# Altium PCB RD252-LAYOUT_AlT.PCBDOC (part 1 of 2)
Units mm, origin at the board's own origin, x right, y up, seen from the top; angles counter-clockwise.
Board outline 55 x 54 mm, 2 copper layers (TOP, BOTTOM), stack 0 mm thick; 81 components, 42 nets, 652 pads, 0 vias.
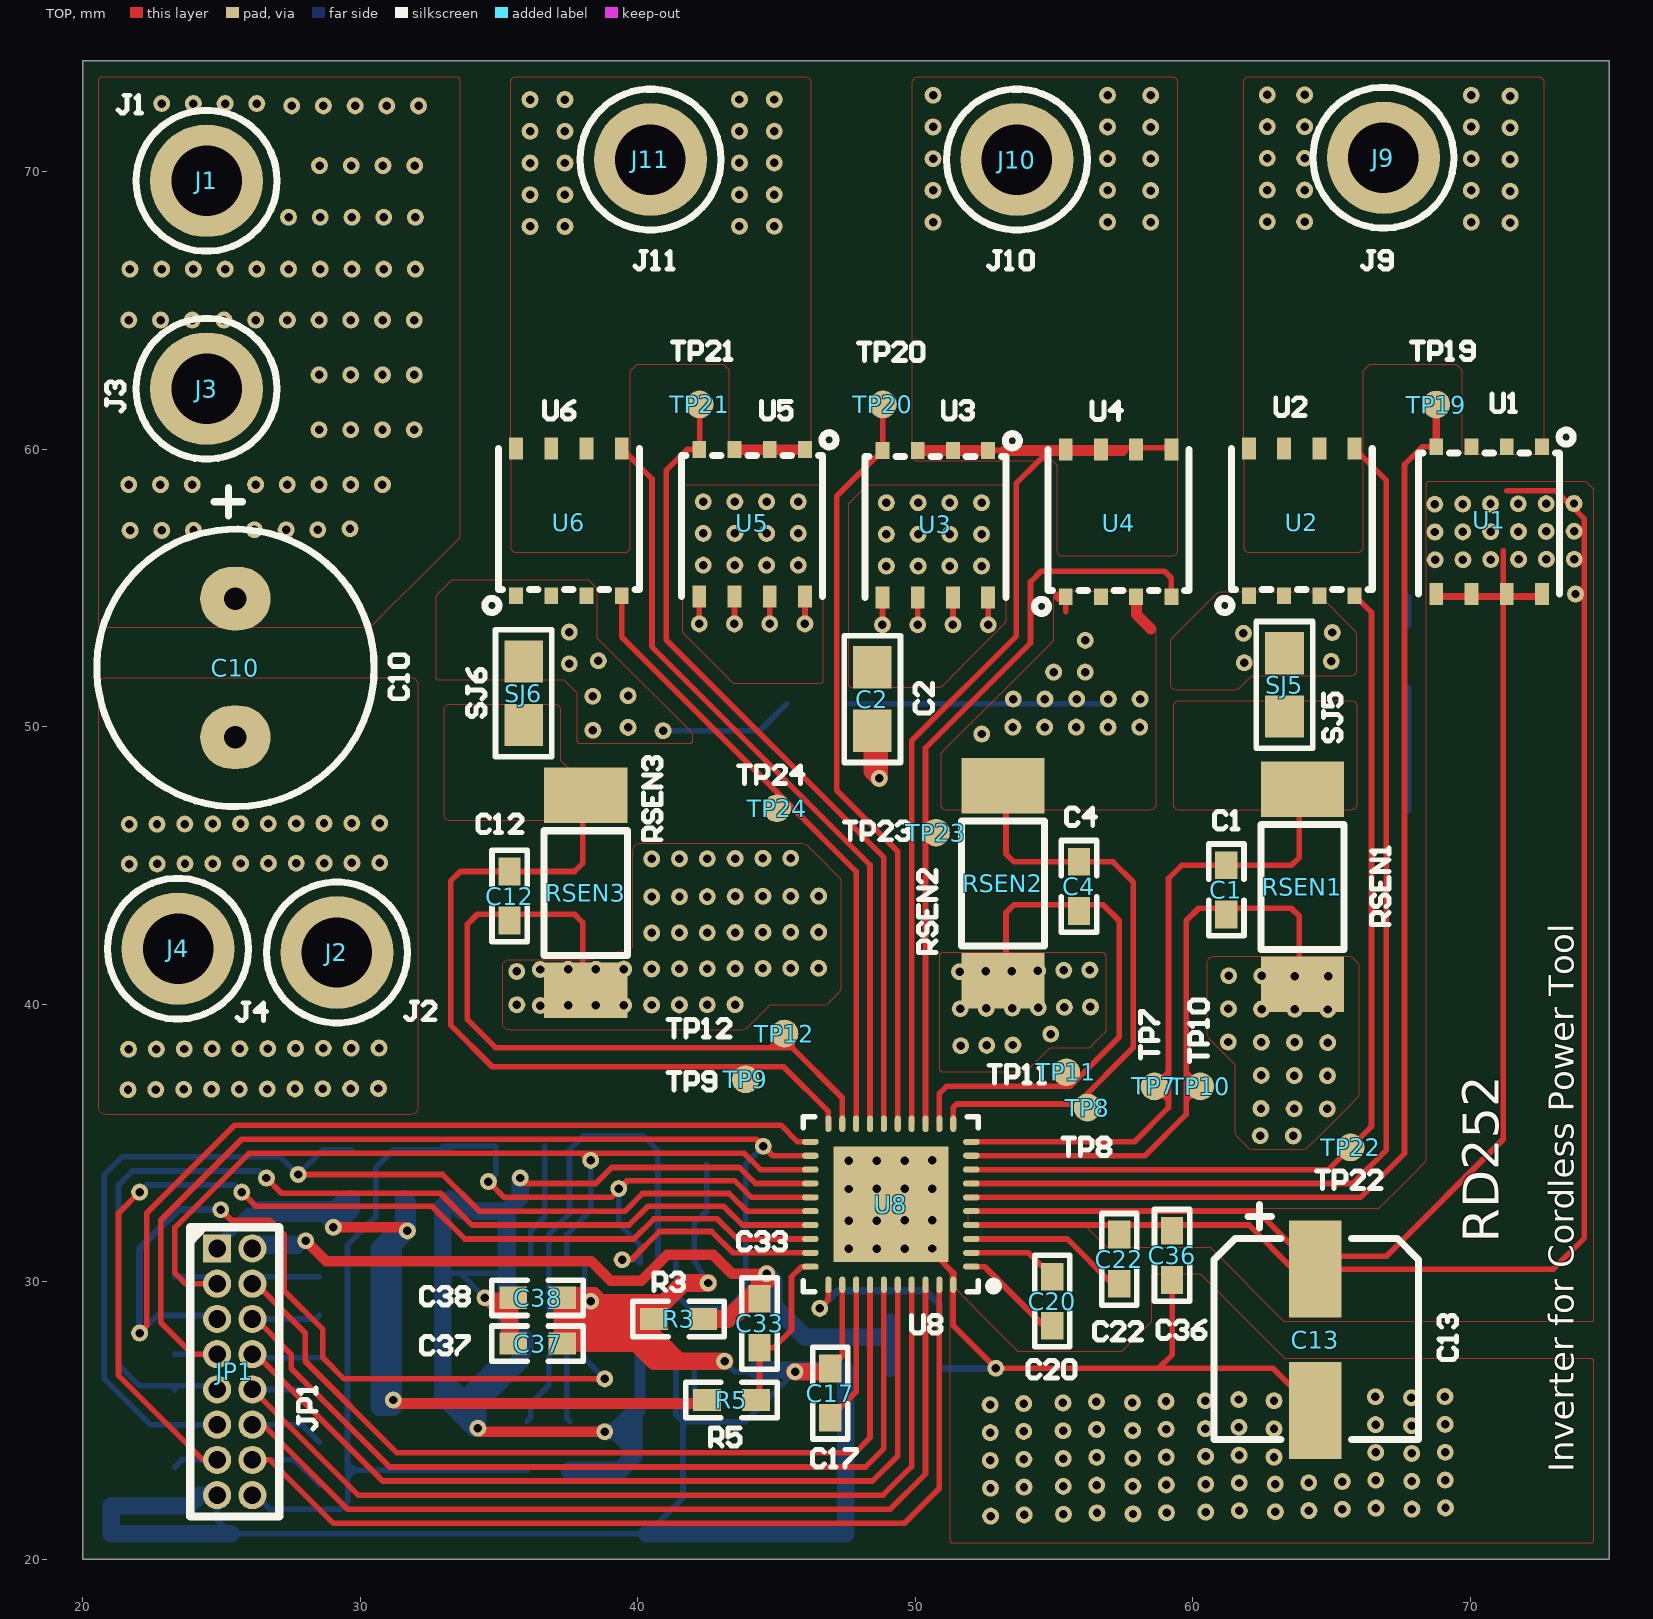
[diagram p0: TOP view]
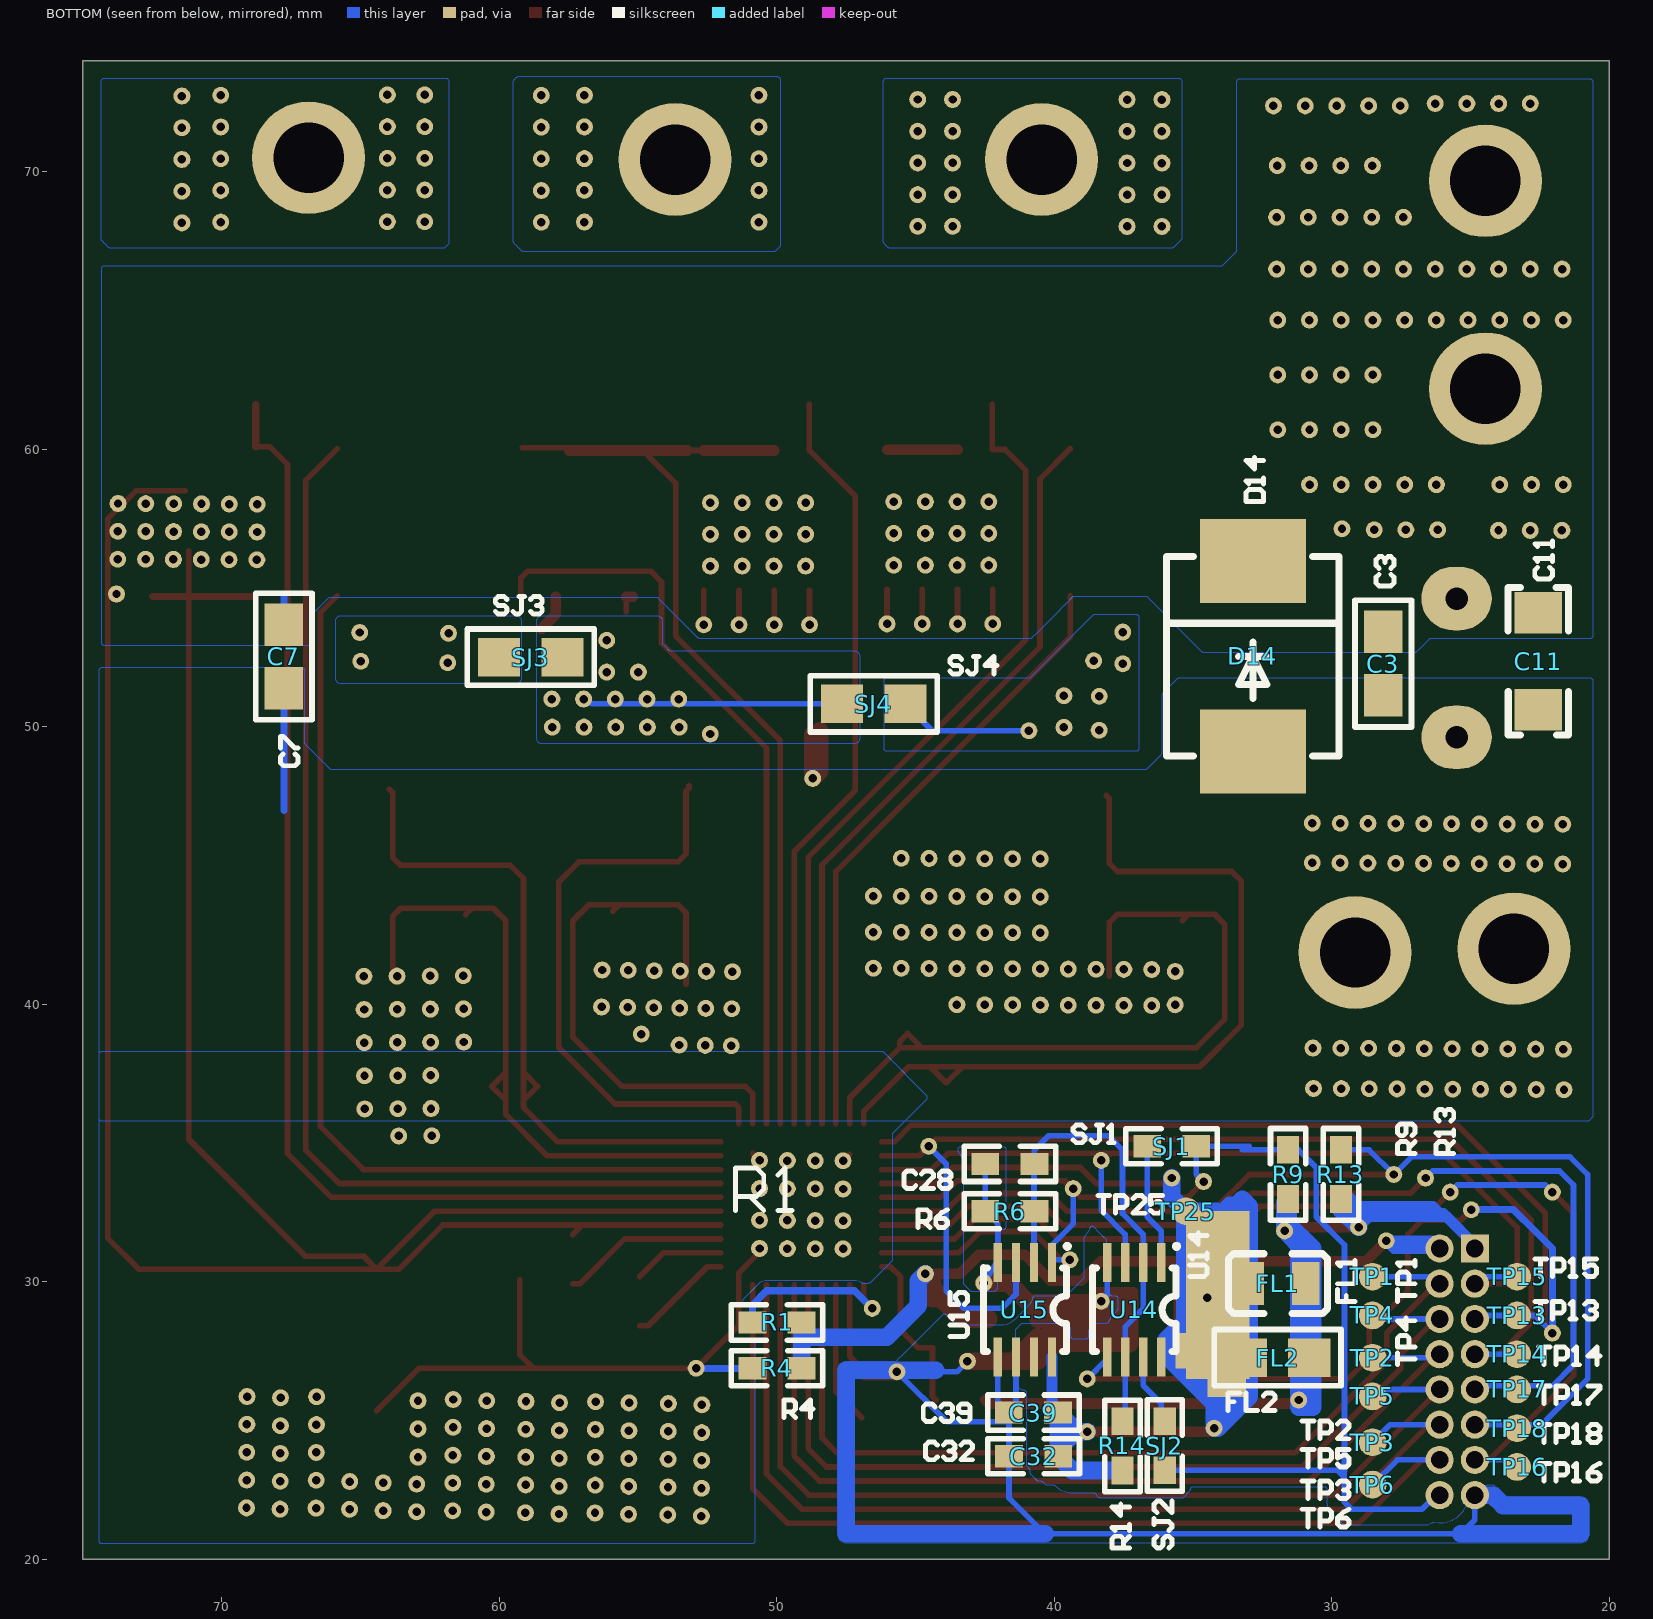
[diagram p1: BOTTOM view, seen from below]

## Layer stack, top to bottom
Top Solder: solder mask 0.0102, Solder Resist, Dk 3.5
TOP: signal copper (thickness not stored)
BOTTOM: signal copper (thickness not stored)
Bottom Solder: solder mask 0.0102, Solder Resist, Dk 3.5

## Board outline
20,20 20,74 75,74 75,20

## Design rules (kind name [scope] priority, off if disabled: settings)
AssemblyTestPointUsage [All] p0: scope1count=1 scope1_0_kind=Board scope1_0_value=Board scope2count=1 scope2_0_kind=Board scope2_0_value=Board commentlength=0
AssemblyTestpoint [All] p0: scope1count=1 scope1_0_kind=Board scope1_0_value=Board scope2count=1 scope2_0_kind=Board scope2_0_value=Board commentlength=0
Clearance [All] p0: scope1count=1 scope1_0_kind=Board scope1_0_value=Board scope2count=1 scope2_0_kind=Board scope2_0_value=Board commentlength=0 gap=0.15
Clearance [All] p1: gap=0.15 ignorepadtopadclearanceinfootprint=TRUE except(0.2: SMDPad-Fill SMDPad-Poly SMDPad-Region THPad-Fill THPad-Poly THPad-Region; 0.3: Arc-Hole Track-Hole SMDPad-Hole THPad-Hole Via-Hole Fill-Hole Poly-Hole Region-Hole Text-Hole)
ComponentClearance [All] p0: scope1count=1 scope1_0_kind=Board scope1_0_value=Board scope2count=1 scope2_0_kind=Board scope2_0_value=Board commentlength=0 gap=0.254 collisioncheckmode=3
DiffPairsRouting [All] p0: scope1count=1 scope1_0_kind=Board scope1_0_value=Board scope2count=1 scope2_0_kind=Board scope2_0_value=Board commentlength=0
FabricationTestPointUsage [All] p0: scope1count=1 scope1_0_kind=Board scope1_0_value=Board scope2count=1 scope2_0_kind=Board scope2_0_value=Board commentlength=0 valid=0 allowmultiple=FALSE
FabricationTestpoint [All] p0: scope1count=1 scope1_0_kind=Board scope1_0_value=Board scope2count=1 scope2_0_kind=Board scope2_0_value=Board commentlength=0 side=3 testpointundercomponent=TRUE minsize=1.016 maxsize=2.54 preferedsize=1.524 minholesize=0 maxholesize=1.016 preferedholesize=0.813 testpointgrid=0.025
FanoutControl Fanout_Default [All] p0: scope1count=1 scope1_0_kind=Board scope1_0_value=Board scope2count=1 scope2_0_kind=Board scope2_0_value=Board commentlength=30 // Fanout_Default (Default Rule)
FanoutControl Fanout_Small [All] p0 off: scope1count=1 scope1_0_kind=Board scope1_0_value=Board scope2count=1 scope2_0_kind=Board scope2_0_value=Board commentlength=84 // Protel DXP Scope 1 Expression Was: (CompPinCount < 5)   Fanout_Small (Default Rule)
FanoutControl Fanout_SOIC [All] p0 off: scope1count=1 scope1_0_kind=Board scope1_0_value=Board scope2count=1 scope2_0_kind=Board scope2_0_value=Board commentlength=71 // Protel DXP Scope 1 Expression Was: IsSOIC   Fanout_SOIC (Default Rule)
FanoutControl Fanout_LCC [All] p0 off: scope1count=1 scope1_0_kind=Board scope1_0_value=Board scope2count=1 scope2_0_kind=Board scope2_0_value=Board commentlength=69 // Protel DXP Scope 1 Expression Was: IsLCC   Fanout_LCC (Default Rule)
FanoutControl Fanout_BGA [All] p0 off: scope1count=1 scope1_0_kind=Board scope1_0_value=Board scope2count=1 scope2_0_kind=Board scope2_0_value=Board commentlength=69 // Protel DXP Scope 1 Expression Was: IsBGA   Fanout_BGA (Default Rule)
Height [All] p0: scope1count=1 scope1_0_kind=Board scope1_0_value=Board scope2count=1 scope2_0_kind=Board scope2_0_value=Board commentlength=0
HoleSize [All] p0: scope1count=1 scope1_0_kind=Board scope1_0_value=Board scope2count=1 scope2_0_kind=Board scope2_0_value=Board commentlength=0 absolutevalues=TRUE maxlimit=100 minlimit=0.001 maxpercent=80.000 minpercent=20.000
HoleSize [All] p1: absolutevalues=TRUE maxlimit=100 minlimit=0.001 maxpercent=80.000 minpercent=20.000
HoleToHoleClearance [All] p0: scope1count=1 scope1_0_kind=Board scope1_0_value=Board scope2count=1 scope2_0_kind=Board scope2_0_value=Board commentlength=0
HoleToHoleClearance [All] p1: gap=0.4 allowstackedmicrovias=FALSE
LayerPairs [All] p0: scope1count=1 scope1_0_kind=Board scope1_0_value=Board scope2count=1 scope2_0_kind=Board scope2_0_value=Board commentlength=0 enforce=TRUE
MinimumSolderMaskSliver [All] p0: scope1count=1 scope1_0_kind=Board scope1_0_value=Board scope2count=1 scope2_0_kind=Board scope2_0_value=Board commentlength=0
MinimumSolderMaskSliver [All] p1: minsoldermaskwidth=0.1
NetAntennae [All] p0: scope1count=1 scope1_0_kind=Board scope1_0_value=Board scope2count=1 scope2_0_kind=Board scope2_0_value=Board commentlength=0
NetAntennae [All] p1: netantennaetolerance=100
PasteMaskExpansion [All] p0: scope1count=1 scope1_0_kind=Board scope1_0_value=Board scope2count=1 scope2_0_kind=Board scope2_0_value=Board commentlength=0 expansion=0
PlaneClearance [All] p0: scope1count=1 scope1_0_kind=Board scope1_0_value=Board scope2count=1 scope2_0_kind=Board scope2_0_value=Board commentlength=0 clearance=0.001
PlaneClearance [All] p1: clearance=0.001
PlaneConnect [All] p0: scope1count=1 scope1_0_kind=Board scope1_0_value=Board scope2count=1 scope2_0_kind=Board scope2_0_value=Board commentlength=0 planeconnectstyle=Direct reliefexpansion=0.508 reliefentries=4 reliefconductorwidth=0.254 reliefairgap=0.254
PlaneConnect [All] p1: planeconnectstyle=Direct reliefexpansion=0.508 reliefentries=4 reliefconductorwidth=0.254 reliefairgap=0.254
PolygonConnect [All] p0: scope1count=1 scope1_0_kind=Board scope1_0_value=Board scope2count=1 scope2_0_kind=Board scope2_0_value=Board commentlength=0 connectstyle=Direct reliefconductorwidth=0.254 reliefentries=4 polygonreliefangle="90 Angle"
PolygonConnect [All] p1: connectstyle=Direct reliefconductorwidth=0.254 reliefentries=4 polygonreliefangle="90 Angle" airgapwidth=0.254
RoutingCorners [All] p0: scope1count=1 scope1_0_kind=Board scope1_0_value=Board scope2count=1 scope2_0_kind=Board scope2_0_value=Board commentlength=0 cornerstyle=45-Degree minsetback=2.54 maxsetback=2.54
RoutingLayers [All] p0: scope1count=1 scope1_0_kind=Board scope1_0_value=Board scope2count=1 scope2_0_kind=Board scope2_0_value=Board commentlength=0 top layer=Automatic bottom layer=Automatic
RoutingPriority [All] p0: scope1count=1 scope1_0_kind=Board scope1_0_value=Board scope2count=1 scope2_0_kind=Board scope2_0_value=Board commentlength=0
RoutingTopology [All] p0: scope1count=1 scope1_0_kind=Board scope1_0_value=Board scope2count=1 scope2_0_kind=Board scope2_0_value=Board commentlength=0 topology=Shortest
RoutingVias [All] p0: scope1count=1 scope1_0_kind=Board scope1_0_value=Board scope2count=1 scope2_0_kind=Board scope2_0_value=Board commentlength=0 holewidth=0.1 width=0.1 viastyle="Through Hole" minholewidth=0.001 minwidth=0.001 maxholewidth=100 maxwidth=100
RoutingVias [All] p1: holewidth=0.1 width=0.1 viastyle="Through Hole" minholewidth=0.001 minwidth=0.001 maxholewidth=100 maxwidth=100
ShortCircuit [All] p0: scope1count=1 scope1_0_kind=Board scope1_0_value=Board scope2count=1 scope2_0_kind=Board scope2_0_value=Board commentlength=0 allowed=FALSE
SilkToBoardRegionClearance [All] p0: scope1count=1 scope1_0_kind=Board scope1_0_value=Board scope2count=1 scope2_0_kind=Board scope2_0_value=Board commentlength=0
SilkToSilkClearance [All] p0: scope1count=1 scope1_0_kind=Board scope1_0_value=Board scope2count=1 scope2_0_kind=Board scope2_0_value=Board commentlength=0
SilkToSilkClearance [All] p1: silktosilkclearance=0.001
SilkToSolderMaskClearance [All] p0 off: scope1count=1 scope1_0_kind=Board scope1_0_value=Board scope2count=1 scope2_0_kind=Board scope2_0_value=Board commentlength=44 // Protel DXP Scope 1 Expression Was: IsPad
SilkToSolderMaskClearance [IsPad] p1: minsilkscreentomaskgap=0 clearancetoexposedcopper=TRUE
SolderMaskExpansion [All] p0: scope1count=1 scope1_0_kind=Board scope1_0_value=Board scope2count=1 scope2_0_kind=Board scope2_0_value=Board commentlength=0 expansion=0.001
SolderMaskExpansion [All] p1: expansion=0.001
UnRoutedNet [All] p0: scope1count=1 scope1_0_kind=Board scope1_0_value=Board scope2count=1 scope2_0_kind=Board scope2_0_value=Board commentlength=0
UnpouredPolygon [All] p0: scope1count=1 scope1_0_kind=Board scope1_0_value=Board scope2count=1 scope2_0_kind=Board scope2_0_value=Board commentlength=0
Width [All] p0: scope1count=1 scope1_0_kind=Board scope1_0_value=Board scope2count=1 scope2_0_kind=Board scope2_0_value=Board commentlength=0 maxlimit=1000 minlimit=2539.975 preferedwidth=0
Width [All] p1: maxlimit=1000 minlimit=2539.975 preferedwidth=0 toplayer_minwidth=0 bottomlayer_minwidth=0 minimp=50.000000 maximp=50.000000 favimp=50.000000
22 further rules are at their usual default settings.

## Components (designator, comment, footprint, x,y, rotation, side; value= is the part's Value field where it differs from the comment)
C1 "0603" 0603#1 61.208,45.009 r270 top
C2 "0805" 0805#1 48.448,52.147 r270 top
C3 "0805" 0805#2 28.137,53.426 r90 bottom
C4 "0603" 0603#1 55.899,45.136 r270 top
C7 "0805" 0805#2 67.761,53.68 r90 bottom
C10 "CAP_10MM" CAP_10MM 25.495,54.626 r180 top
C11 "1206" 1206 22.549,54.115 r270 bottom
C12 "0603" 0603#1 35.376,44.79 r270 top
C13 "CASE_B2" CASE_B2 64.416,30.455 r270 top
C17 "0603" 0603#1 46.933,25.105 r90 top
C20 "0603" 0603#1 54.934,30.185 r270 top
C22 "0603" 0603#1 57.347,29.931 r90 top
C32 "0603" 0603#2 39.853,23.711 r180 bottom
C33 "0603" 0603#1 44.384,27.62 r90 top
C36 "0603" 0603#1 59.252,31.836 r270 top
C37 "0603" 0603#1 35.503,27.772 r0 top
C38 "0603" 0603#1 35.503,29.423 r0 top
C39 "0603" 0603#2 39.861,25.286 r180 bottom
D14 "DSMC" DSMC 32.836,49.108 r90 bottom
FL1 "L0805" L0805 30.931,29.931 r180 bottom
FL2 "0805" 0805#2 33.09,27.264 r0 bottom
J1 "TP_SM" TP_SM 24.454,69.682 r180 top
J2 "TP_SM" TP_SM 29.153,41.869 r180 top
J3 "TP_SM" TP_SM 24.454,62.189 r0 top
J4 "TP_SM" TP_SM 23.425,42.004 r0 top
J9 "TP_SM" TP_SM 66.869,70.514 r0 top
J10 "TP_SM" TP_SM 53.661,70.446 r0 top
J11 "TP_SM" TP_SM 40.453,70.446 r0 top
JP1 "IDC16_1.27MM" IDC16_1.27MM 24.835,31.201 r270 top
R1 "0603" 0603#2 50.87,28.534 r0 bottom
R3 "0603" 0603#1 40.583,28.661 r0 top
R4 "0603" 0603#2 49.104,26.883 r180 bottom
R5 "0603" 0603#1 42.488,25.74 r0 top
R6 "0603" 0603#2 40.71,32.545 r180 bottom
R9 "0603" 0603#2 31.566,34.757 r90 bottom
R13 "0603" 0603#2 29.661,34.757 r90 bottom
R14 "0603" 0603#2 37.535,23.2 r270 bottom
RSEN1 "2512" 2512 63.951,40.726 r270 top
RSEN2 "2512" 2512 53.156,40.853 r270 top
RSEN3 "2512" 2512 38.119,40.507 r270 top
SJ1 "0603" 0603#2 36.646,34.884 r0 bottom
SJ2 "0603" 0603#2 36.011,24.978 r90 bottom
SJ3 "0805" 0805#2 60.006,52.514 r0 bottom
SJ4 "0805" 0805#2 47.644,50.83 r0 bottom
SJ5 "0805" 0805#1 63.307,50.371 r90 top
SJ6 "0805" 0805#1 35.883,50.068 r90 top
TP1 "TP2" TP2 28.518,30.185 r180 bottom
TP2 "TP2" TP2 28.518,27.264 r180 bottom
TP3 "TP2" TP2 28.518,24.216 r180 bottom
TP4 "TP2" TP2 28.518,28.788 r90 bottom
TP5 "TP2" TP2 28.518,25.867 r90 bottom
TP6 "TP2" TP2 28.518,22.692 r90 bottom
TP7 "TP2" TP2 58.617,37.043 r0 top
TP8 "TP2" TP2 56.204,36.281 r180 top
TP9 "TP2" TP2 43.885,37.297 r180 top
TP10 "TP2" TP2 60.268,37.043 r180 top
TP11 "TP2" TP2 55.442,37.551 r180 top
TP12 "TP2" TP2 45.282,38.948 r270 top
TP13 "TP2" TP2 23.311,28.788 r270 bottom
TP14 "TP2" TP2 23.311,27.391 r270 bottom
TP15 "TP2" TP2 23.311,30.185 r270 bottom
TP16 "TP2" TP2 23.311,23.327 r270 bottom
TP17 "TP2" TP2 23.311,26.121 r270 bottom
TP18 "TP2" TP2 23.311,24.724 r270 bottom
TP19 "TP2" TP2 68.774,61.617 r0 top
TP20 "TP2" TP2 48.829,61.621 r180 top
TP21 "TP2" TP2 42.225,61.621 r180 top
TP22 "TP2" TP2 65.687,34.842 r180 top
TP23 "TP2" TP2 50.743,46.187 r180 top
TP24 "TP2" TP2 45.019,47.067 r180 top
TP25 "TP2" TP2 35.249,32.545 r270 bottom
U1 "SOP-8T" SOP-8T 72.584,60.093 r0 top
U2 "SOP-8T" SOP-8T 62.022,54.729 r180 top
U3 "SOP-8T" SOP-8T 52.624,59.961 r0 top
U4 "SOP-8T" SOP-8T 55.418,54.695 r180 top
U5 "SOP-8T_1" SOP-8T_1 46.02,59.995 r0 top
U6 "SOP-8T" SOP-8T 35.607,54.729 r180 top
U8 "WQFN-40" WQFN-40 52.016,30.545 r180 top
U14 "SSOP-8" SSOP-8 36.138,30.693 r180 bottom
U15 "SSOP-8" SSOP-8 40.075,30.693 r180 bottom
? "0603" 0603#2 40.71,34.249 r180 bottom

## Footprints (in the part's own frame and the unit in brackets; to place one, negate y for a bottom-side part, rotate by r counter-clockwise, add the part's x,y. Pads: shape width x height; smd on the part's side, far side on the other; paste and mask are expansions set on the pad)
0603#1 [mm] "KC00080BKP"
  rect 1x0.8 smd paste-1.203 mask+0: 1(0,0) 2(1.77,0)
0603#2 [mm] "KC00080BKP"
  rect 1x0.8 smd paste-1.203 mask+0: 1(0,0) 2(-1.77,0)
0805#1 [mil] "KC00080BKP"
  rect 60x55 smd paste-68 mask+0: 1(0,0) 2(90,0)
0805#2 [mil] "KC00080BKP"
  rect 60x55 smd paste-68 mask+0: 1(0,0) 2(-90,0)
1206 [mm] "KC00080BKP"
  rect 1.5x1.7 smd paste-1.903 mask+0: 1(0,0) 2(3.5,0)
2512 [mm] "KC00080BKP"
  rect 2x3 smd paste-3.203 mask+0: 1(0,0) 2(-7.021,0)
CAP_10MM [mil] "KC00080BKP"
  oval 100x90 / inner round 0 / far side oval 100x90 hole 32 paste-108 mask+0: 1(0,0) 2(0,196.85)
CASE_B2 [mm] "KC00080BKP"
  rect 3.5x1.9 smd paste-3.6 mask+0: 1(0,0) 2(5.1,0)
DSMC [mm] "KC00080BKP"
  rect 3.03x3.82 smd paste-4.023 mask+0: A(0,0) C(6.87,0)
IDC16_1.27MM [mil] "KC00080BKP"
  rect 40x40 / inner round 0 / far side rect 40x40 hole 25 paste-48 mask+0: 1(0,0)
  round 40 / inner round 0 / far side round 40 hole 25 paste-48 mask+0: 2(0,50) 3(50,0) 4(50,50) 5(100,0) 6(100,50) 7(150,0) 8(150,50) 9(200,0) 10(200,50) 11(250,0) 12(250,50) 13(300,0) 14(300,50) 15(350,0) 16(350,50)
L0805 [mm] "KC00080BKP"
  rect 1x1.55 smd paste-1.753 mask+0: 1(0,0) 2(-2,0)
SOP-8T [mm] "KC00080BKP"
  rect 0.5x0.6 smd paste-0.803 mask+0: 1(0,0) 2(-1.27,0) 3(-2.54,0) 4(-3.81,0)
  rect 0.5x0.8 smd paste-1.003 mask+0: 5(-3.81,-5.3) 6(-2.54,-5.3) 7(-1.27,-5.3) 8(0,-5.3)
SOP-8T_1 [mm] "KC00080BKP"
  rect 0.5x0.6 smd paste-0.803 mask+0: 1(0,0) 2(-1.27,0) 3(-2.54,0) 4(-3.81,0)
  rect 0.5x0.8 smd paste-1.003 mask+0: 5(-3.81,-5.3) 6(-2.54,-5.3) 7(-1.27,-5.3) 8(0,-5.3)
SSOP-8 [mm] "KC00080BKP"
  rect 0.3x1.4 smd paste-1.603 mask+0: 1(0,0) 2(-0.65,0) 3(-1.3,0) 4(-1.95,0) 5(-1.95,-3.4) 6(-1.3,-3.4) 7(-0.65,-3.4) 8(0,-3.4)
TP2 [mm] "KC00080BKP"
  round 1 smd paste-1.203 mask+0: 1(0,0)
TP_SM [mil] "KC00080BKP"
  round 160 / inner round 0 / far side round 160 hole 100 paste-168 mask+0: 1(0,0)
WQFN-40 [mm] "KC00080BKP"
  oval 0.6x0.22 smd paste-0.803 mask+0: 1(0,0) 2(0,-0.5) 3(0,-1) 4(0,-1.5) 5(0,-2) 6(0,-2.5) 7(0,-3) 8(0,-3.5) 9(0,-4) 10(0,-4.5) 21(5.8,-4.5) 22(5.8,-4) 23(5.8,-3.5) 24(5.8,-3) 25(5.8,-2.5) 26(5.8,-2) 27(5.8,-1.5) 28(5.8,-1) 29(5.8,-0.5) 30(5.8,0)
  oval 0.22x0.6 smd paste-0.803 mask+0: 11(0.65,-5.15) 12(1.15,-5.15) 13(1.65,-5.15) 14(2.15,-5.15) 15(2.65,-5.15) 16(3.15,-5.15) 17(3.65,-5.15) 18(4.15,-5.15) 19(4.65,-5.15) 20(5.15,-5.15) 31(5.15,0.65) 32(4.65,0.65) 33(4.15,0.65) 34(3.65,0.65) 35(3.15,0.65) 36(2.65,0.65) 37(2.15,0.65) 38(1.65,0.65) 39(1.15,0.65) 40(0.65,0.65)
  rect 4.15x4.15 smd paste-4.353 mask+0: 41(2.9,-2.25)

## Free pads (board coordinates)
  round 0.61 / inner round 0 / far side round 0.61 hole 0.305 paste-0.813 mask+0: ""(21.623,36.924) ""(21.643,38.381) ""(21.649,58.732) ""(21.653,64.663) ""(21.665,46.489) ""(21.67,45.057) ""(21.693,66.5) ""(21.697,57.081) ""(22.041,28.153) ""(22.041,33.233) ""(22.626,36.929) ""(22.646,38.386) ""(22.668,46.494) ""(22.673,45.062) ""(22.792,58.732) ""(22.796,64.663) ""(22.836,66.5) ""(22.836,72.466) ""(22.84,57.081) ""(23.629,36.934) ""(23.649,38.391) ""(23.671,46.499) ""(23.676,45.067) ""(23.935,58.732) ""(23.939,64.663) ""(23.979,66.5) ""(23.979,72.466) ""(23.983,57.081) ""(24.632,36.939) ""(24.652,38.396) ""(24.674,46.503) ""(24.679,45.071) ""(24.962,32.598) ""(25.082,64.663) ""(25.122,66.5) ""(25.122,72.466) ""(25.635,36.943) ""(25.655,38.4) ""(25.677,46.508) ""(25.682,45.076) ""(25.724,33.233) ""(26.178,57.107) ""(26.221,58.732) ""(26.225,64.663) ""(26.265,66.5) ""(26.265,72.466) ""(26.613,33.741) ""(26.638,36.948) ""(26.658,38.405) ""(26.68,46.513) ""(26.685,45.081) ""(27.321,57.107) ""(27.364,58.732) ""(27.368,64.663) ""(27.408,66.5) ""(27.409,68.367) ""(27.522,72.382) ""(27.641,36.953) ""(27.661,38.41) ""(27.683,46.518) ""(27.688,45.086) ""(27.756,33.868) ""(28.026,31.481) ""(28.464,57.107) ""(28.507,58.732) ""(28.508,60.709) ""(28.509,62.686) ""(28.511,64.663) ""(28.526,70.229) ""(28.551,66.5) ""(28.552,68.367) ""(28.644,36.958) ""(28.664,38.415) ""(28.665,72.382) ""(28.686,46.523) ""(28.691,45.091) ""(29.026,31.963) ""(29.624,57.139) ""(29.646,36.963) ""(29.65,58.732) ""(29.651,60.709) ""(29.652,62.686) ""(29.654,64.663) ""(29.667,38.42) ""(29.669,70.229) ""(29.689,46.527) ""(29.694,45.095) ""(29.694,66.5) ""(29.695,68.367) ""(29.808,72.382) ""(30.649,36.968) ""(30.67,38.425) ""(30.692,46.532) ""(30.697,45.1) ""(30.793,58.732) ""(30.794,60.709) ""(30.795,62.686) ""(30.797,64.663) ""(30.812,70.229) ""(30.837,66.5) ""(30.838,68.367) ""(30.951,72.382) ""(31.185,25.74) ""(31.693,31.836) ""(31.937,60.709) ""(31.938,62.686) ""(31.94,64.663) ""(31.955,70.229) ""(31.98,66.5) ""(31.981,68.367) ""(32.094,72.382) ""(34.233,24.724) ""(34.487,29.423) ""(34.614,33.614) ""(35.633,41.186) ""(35.638,39.984) ""(35.757,33.741) ""(36.114,68.036) ""(36.114,69.179) ""(36.114,70.322) ""(36.114,71.465) ""(36.114,72.608) ""(36.482,39.957) ""(36.482,41.256) ""(37.371,68.037) ""(37.371,69.18) ""(37.371,70.323) ""(37.371,71.466) ""(37.371,72.609) ""(37.484,39.961) ""(37.485,41.261) ""(37.526,52.274) ""(37.526,53.417) ""(38.297,29.296) ""(38.297,34.376) ""(38.37,51.102) ""(38.378,49.878) ""(38.487,39.966) ""(38.488,41.265) ""(38.576,52.385) ""(38.805,24.597) ""(38.805,26.502) ""(39.313,33.36) ""(39.431,30.795) ""(39.49,39.971) ""(39.491,41.27) ""(39.645,49.982) ""(39.645,51.125) ""(40.493,39.976) ""(40.494,41.275) ""(40.495,42.574) ""(40.495,45.241) ""(40.496,43.873) ""(40.908,49.863) ""(41.496,39.981) ""(41.497,41.28) ""(41.498,42.579) ""(41.498,45.246) ""(41.499,43.878) ""(42.21,53.712) ""(42.352,55.83) ""(42.352,56.973) ""(42.352,58.116) ""(42.499,39.985) ""(42.5,41.285) ""(42.501,42.584) ""(42.501,45.251) ""(42.502,43.883) ""(42.53,29.957) ""(43.123,27.137) ""(43.48,53.712) ""(43.495,55.83) ""(43.495,56.973) ""(43.495,58.116) ""(43.502,39.99) ""(43.503,41.289) ""(43.504,42.589) ""(43.504,45.256) ""(43.505,43.888) ""(43.66,68.04) ""(43.66,69.183) ""(43.66,70.326) ""(43.66,71.469) ""(43.66,72.612) ""(44.506,41.294) ""(44.507,42.593) ""(44.507,45.26) ""(44.508,43.893) ""(44.52,34.884) ""(44.638,30.287) ""(44.638,55.83) ""(44.638,56.973) ""(44.638,58.116) ""(44.75,53.712) ""(44.918,68.04) ""(44.918,69.183) ""(44.918,70.326) ""(44.918,71.469) ""(44.918,72.612) ""(45.509,41.299) ""(45.51,42.598) ""(45.51,45.265) ""(45.511,43.897) ""(45.663,26.756) ""(45.781,55.83) ""(45.781,56.973) ""(45.781,58.116) ""(46.02,53.712) ""(46.512,41.304) ""(46.513,42.603) ""(46.514,43.902) ""(46.552,29.042) ""(47.607,31.187) ""(47.607,32.203) ""(47.607,33.346) ""(47.607,34.362) ""(48.61,31.191) ""(48.61,32.207) ""(48.61,33.35) ""(48.61,34.366) ""(48.702,48.143) ""(48.814,53.678) ""(48.956,55.796) ""(48.956,56.939) ""(48.956,58.082) ""(49.613,31.196) ""(49.613,32.212) ""(49.613,33.355) ""(49.613,34.371) ""(50.084,53.678) ""(50.099,55.796) ""(50.099,56.939) ""(50.099,58.082) ""(50.616,31.201) ""(50.616,32.217) ""(50.616,33.36) ""(50.616,34.376) ""(50.638,68.193) ""(50.638,69.336) ""(50.638,70.479) ""(50.638,71.622) ""(50.638,72.765) ""(51.242,55.796) ""(51.242,56.939) ""(51.242,58.082) ""(51.354,53.678) ""(51.593,41.174) ""(51.615,39.841) ""(51.636,38.509) ""(52.385,55.796) ""(52.385,56.939) ""(52.385,58.082) ""(52.394,49.743) ""(52.532,41.187) ""(52.554,39.854) ""(52.575,38.521) ""(52.624,53.678) ""(52.693,25.567) ""(52.698,24.564) ""(52.703,23.561) ""(52.708,22.558) ""(52.712,21.555) ""(52.902,26.883) ""(53.472,41.2) ""(53.493,39.867) ""(53.514,49.991) ""(53.515,38.534) ""(53.528,51.004) ""(53.901,25.612) ""(53.906,24.609) ""(53.911,23.606) ""(53.916,22.603) ""(53.92,21.6) ""(54.411,41.212) ""(54.433,39.88) ""(54.657,49.991) ""(54.671,51.004) ""(54.88,38.93) ""(54.983,51.975) ""(55.319,25.636) ""(55.323,24.633) ""(55.328,23.63) ""(55.333,22.627) ""(55.338,21.624) ""(55.35,41.225) ""(55.372,39.892) ""(55.8,49.991) ""(55.814,51.004) ""(56.126,51.975) ""(56.126,53.118) ""(56.29,41.238) ""(56.311,39.905) ""(56.526,25.681) ""(56.531,24.678) ""(56.536,23.675) ""(56.541,22.672) ""(56.546,21.669) ""(56.927,68.195) ""(56.927,69.338) ""(56.927,70.481) ""(56.927,71.624) ""(56.927,72.767) ""(56.943,49.991) ""(56.957,51.004) ""(57.825,25.644) ""(57.83,24.641) ""(57.835,23.638) ""(57.839,22.635) ""(57.844,21.632) ""(58.086,49.991) ""(58.1,51.004) ""(58.48,68.187) ""(58.48,69.33) ""(58.48,70.473) ""(58.48,71.616) ""(58.48,72.759) ""(59.033,25.689) ""(59.038,24.686) ""(59.043,23.683) ""(59.047,22.68) ""(59.052,21.677) ""(60.45,25.713) ""(60.455,24.71) ""(60.46,23.707) ""(60.465,22.704) ""(60.47,21.701) ""(61.277,38.642) ""(61.284,39.837) ""(61.291,41.032) ""(61.658,25.758) ""(61.663,24.755) ""(61.668,23.752) ""(61.673,22.749) ""(61.677,21.746) ""(61.824,53.373) ""(61.852,52.313) ""(62.427,35.265) ""(62.457,36.245) ""(62.464,37.44) ""(62.471,38.635) ""(62.479,39.83) ""(62.486,41.024) ""(62.684,68.205) ""(62.684,69.348) ""(62.684,70.491) ""(62.684,71.634) ""(62.684,72.777) ""(62.926,23.683) ""(62.926,24.699) ""(62.926,25.715) ""(62.971,22.712) ""(62.976,21.709) ""(63.622,35.258) ""(63.651,36.238) ""(63.659,37.433) ""(63.666,38.627) ""(63.673,39.822) ""(63.681,41.017) ""(64.03,68.206) ""(64.03,69.349) ""(64.03,70.492) ""(64.03,71.635) ""(64.03,72.778) ""(64.179,22.757) ""(64.184,21.754) ""(64.846,36.231) ""(64.853,37.425) ""(64.861,38.62) ""(64.868,39.815) ""(64.876,41.01) ""(64.987,52.365) ""(65.028,53.402) ""(65.387,22.802) ""(65.392,21.799) ""(66.58,25.856) ""(66.585,24.853) ""(66.59,23.85) ""(66.595,22.847) ""(66.6,21.844) ""(67.879,25.819) ""(67.884,24.816) ""(67.889,23.813) ""(67.894,22.81) ""(67.898,21.807) ""(68.723,58.027) ""(68.728,57.024) ""(68.732,56.021) ""(69.087,25.864) ""(69.092,24.861) ""(69.097,23.858) ""(69.101,22.855) ""(69.106,21.852) ""(69.726,58.032) ""(69.73,57.029) ""(69.735,56.026) ""(70.037,68.194) ""(70.037,69.337) ""(70.037,70.48) ""(70.037,71.623) ""(70.037,72.766) ""(70.729,58.037) ""(70.733,57.034) ""(70.738,56.031) ""(71.434,68.165) ""(71.434,69.308) ""(71.434,70.451) ""(71.434,71.594) ""(71.434,72.737) ""(71.732,58.042) ""(71.736,57.039) ""(71.741,56.036) ""(72.735,58.046) ""(72.739,57.043) ""(72.744,56.04) ""(73.738,58.051) ""(73.742,57.048) ""(73.747,56.045) ""(73.792,54.789)
  rect 1.381x1.413 smd far side paste-1.413 mask+0: ""(33.78,26.557)
  rect 2.286x6.043 smd far side paste-6.043 mask+0: ""(34.106,29.524)
  rect 0.762x1.27 smd far side paste-1.27 mask+0: ""(35.249,27.518)

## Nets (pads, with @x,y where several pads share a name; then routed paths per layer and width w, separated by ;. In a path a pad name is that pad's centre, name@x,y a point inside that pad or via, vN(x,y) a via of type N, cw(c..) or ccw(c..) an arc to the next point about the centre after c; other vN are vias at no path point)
+5V: FL1.1 FL2.2 JP1.1 pad.@29.026,31.963 pad.@31.185,25.74 pad.@31.693,31.836 R5.1 R9.2 R13.2 | length 51.1
  TOP w0.381: pad.@29.026,31.963 31.566,31.963 pad.@31.693,31.836 ; pad.@31.185,25.74 31.312,25.613 42.361,25.613 R5.1@42.488,25.74
  BOTTOM w0.203: FL2.2@30.804,27.264 FL1.1@30.804,30.058 ; FL2.2@30.931,26.883 30.931,25.994 pad.@31.185,25.74 ; pad.@31.566,31.709 pad.@31.693,31.836
  BOTTOM w0.381: JP1.1@24.835,31.201 24.835,31.328 25.859,32.352 ; R13.2@29.407,33.106 29.026,32.725 26.359,32.725 26.105,32.471 ; R13.2@29.661,32.987 29.145,32.471 ; FL1.1@30.804,30.058 30.804,30.947 31.185,31.328 ; pad.@31.566,31.709 pad.@31.566,32.09 ; 25.859,32.352 25.978,32.471 26.105,32.471 ; 25.859,32.352 28.637,32.352 ; 26.105,32.471 28.518,32.471 ; 28.518,32.471 28.637,32.352 ; 28.518,32.471 29.145,32.471 ; 28.637,32.352 29.026,32.352 ; 28.637,32.352 pad.@29.026,31.963 29.026,32.352 ; 29.026,32.352 29.145,32.471
  BOTTOM w0.635: pad.@29.026,31.963 29.661,32.598 R13.2@29.661,32.987 ; pad.@31.566,31.709 31.185,31.328 31.185,27.264 pad.@31.185,25.74 31.185,25.486 30.677,25.486 30.677,31.201 30.804,31.328 31.503,32.027 31.566,32.09 R9.2@31.566,32.987 31.693,32.86 pad.@31.693,31.836
+5V_A: C32.1 C37.1 C38.1 C39.1 FL1.2 FL2.1 pad.@33.78,26.557 pad.@34.106,29.524 pad.@34.233,24.724 pad.@34.487,29.423 pad.@35.249,27.518 pad.@35.757,33.741 pad.@38.805,24.597 R14.1 TP25.1 U8.24 U14.8 U15.8 | length 70.7
  TOP w0.203: pad.@34.233,24.724 pad.@34.36,24.597 ; pad.@35.757,33.741 35.953,33.545 38.482,33.545 39.059,34.122 43.664,34.122 44.241,33.545 U8.24@46.216,33.545
  TOP w0.381: pad.@34.36,24.597 pad.@38.805,24.597 ; C37.1@35.249,27.772 35.249,28.661 ; 35.376,28.534 35.249,28.661 ; C37.1@35.503,27.772 C38.1@35.503,29.423 34.995,29.423 ; 34.995,29.423 35.249,29.169 35.249,28.661 ; 34.995,29.423 pad.@34.487,29.423 35.249,28.661
  BOTTOM w0.203: FL1.2@32.963,29.524 FL1.2@32.963,29.931 ; FL1.2@32.963,30.312 pad.@33.598,30.312 ; 33.217,32.979 33.725,32.979 pad.@34.159,32.545 ; 34.233,25.613 36.138,27.518 36.138,28.026 35.503,28.661 35.503,30.312 ; pad.@34.487,29.423 pad.@33.598,30.312 ; TP25.1@35.146,32.365 TP25.1@35.225,32.545 ; TP25.1@35.229,32.554 TP25.1@35.225,32.545 ; TP25.1@35.249,32.545 TP25.1@35.225,32.545 ; TP25.1@35.503,32.471 35.503,30.312 ; 39.059,23.2 39.567,23.708 39.85,23.708 C32.1@39.853,23.711 39.861,23.719 39.861,24.597 ; 39.172,24.597 39.218,24.597 ; 39.853,24.597 39.861,24.597 ; C39.1@40.075,25.5 C39.1@39.861,25.286 39.861,25.113 39.861,24.597 ; pad.@33.598,30.312 35.249,30.312 35.503,30.312
  BOTTOM w0.263: pad.@33.651,32.545 pad.@34.159,32.545
  BOTTOM w0.381: C39.1@39.853,25.105 39.861,25.113 40.075,25.327 40.075,25.5 U15.8@40.075,27.293 ; C39.1@39.853,25.278 C39.1@39.861,25.286
  BOTTOM w0.635: FL1.2@32.963,29.524 32.963,26.502 ; FL1.2@32.963,29.931 32.963,30.312 32.963,32.725 33.217,32.979 pad.@33.651,32.545 ; pad.@33.979,25.994 pad.@34.868,26.883 ; pad.@34.106,24.724 32.963,25.867 32.963,26.502 ; pad.@34.159,32.545 TP25.1@35.225,32.545 ; pad.@34.233,24.724 34.233,25.232 ; pad.@35.757,33.741 35.757,33.053 TP25.1@35.249,32.545 35.249,30.312 35.249,28.407 35.774,27.882 35.774,27.154 35.693,27.074 34.479,25.859 34.233,25.613 34.233,25.232 ; R14.1@37.535,23.2 39.059,23.2 39.342,23.2 C32.1@39.85,23.708 ; pad.@38.805,24.597 39.172,24.597 39.853,25.278 39.853,25.105 39.853,24.597 ; C32.1@39.853,23.711 C32.1@39.853,23.962 ; 32.963,26.502 34.233,25.232 ; C32.1@39.853,23.962 39.218,24.597 39.853,24.597 ; C32.1@39.853,23.962 39.853,24.597
AGND: ?.2 C17.2 C32.2 C37.2 C38.2 C39.2 JP1.15 pad.@38.297,29.296 pad.@42.53,29.957 pad.@43.123,27.137 pad.@45.663,26.756 R3.1 R6.2 U8.32 U14.4 U15.4 U15.5 U15.6 | length 100.5
  TOP w0.203: C38.2@37.273,29.423 38.17,29.423 pad.@38.297,29.296 ; C17.2@46.933,26.875 47.366,27.308 U8.32@47.366,29.895
  TOP w0.381: C38.2@37.145,29.627 38.44,29.627 38.694,29.373 ; 39.812,29.119 38.948,29.119 38.694,29.373 ; 40.955,29.373 38.694,29.373
  TOP w0.635: C37.2@37.273,27.772 37.273,28.255 ; C37.2@37.281,27.78 39.94,27.78 40.583,27.137 41.472,27.137 ; 38.948,29.119 37.577,29.119 C38.2@37.273,29.423 37.273,28.255 ; 39.812,29.119 40.803,29.119 ; R3.1@40.193,29.017 37.654,29.017 37.298,28.661 R3.1@40.345,28.661 ; 40.447,27.874 40.066,28.255 37.273,28.255 ; 40.583,28.026 41.472,27.137 ; R3.1@40.583,28.661 R3.1@40.345,28.661 ; pad.@42.53,29.957 41.641,29.957 40.803,29.119 ; pad.@43.123,27.137 41.472,27.137 ; pad.@45.663,26.756 C17.2@46.814,26.756 ; R3.1@40.345,28.661 40.464,28.78 40.803,29.119
  BOTTOM w0.203: JP1.15@24.835,22.311 24.835,21.422 25.343,20.914 40.329,20.914 41.623,22.208 C32.2@41.623,23.711 C39.2@41.623,24.954 ; U14.4@38.088,30.693 38.088,29.505 pad.@38.297,29.296 ; U15.6@41.375,27.293 C39.2@41.375,25.613 ; U15.5@42.025,27.293 42.025,25.68 C39.2@41.631,25.286 C39.2@41.623,25.278 ; ?.2@42.48,34.249 R6.2@42.48,32.545 42.025,32.09 42.025,30.775 42.062,30.716 pad.@42.53,29.957 ; pad.@43.123,27.137 43.504,26.756 pad.@45.663,26.756 43.861,24.954 C39.2@41.623,24.954 ; C39.2@41.375,25.613 41.623,25.365 C39.2@41.623,25.278 ; C39.2@41.375,25.613 41.375,25.202 41.461,25.116 C39.2@41.623,24.954 ; C39.2@41.623,24.954 C39.2@41.623,25.278
  BOTTOM w0.635: JP1.15@24.835,22.311 24.2,22.311 23.819,21.93 21.025,21.93 21.025,20.914 25.343,20.914 ; 40.329,20.914 47.493,20.914 47.493,26.808 44.264,26.808
AINB10: JP1.3 pad.@38.297,34.376 TP15.1 U8.23 U14.3 | length 33.7
  TOP w0.203: JP1.3@24.835,29.931 23.692,29.931 23.311,30.312 23.311,31.963 25.978,34.63 37.916,34.63 ; pad.@38.297,34.376 37.916,34.63 ; U8.23@46.216,34.045 44.419,34.045 43.834,34.63 37.916,34.63
  BOTTOM w0.203: TP15.1@23.311,30.185 24.581,30.185 JP1.3@24.835,29.931 ; U14.3@37.438,30.693 37.438,31.709 38.297,32.568 pad.@38.297,34.376
AINB11: JP1.7 pad.@44.52,34.884 TP14.1 U8.22 U15.3 | length 42.2
  TOP w0.203: JP1.7@24.835,27.391 23.946,27.391 22.803,28.534 22.803,32.217 25.724,35.138 44.266,35.138 pad.@44.52,34.884 44.859,34.545 U8.22@46.216,34.545
  BOTTOM w0.203: TP14.1@23.311,27.391 JP1.7@24.835,27.391 ; U15.3@41.375,30.693 41.375,29.55 41.883,29.042 43.25,29.042 ; 43.266,29.042 43.25,29.042 ; pad.@44.52,34.884 43.885,34.249 43.885,29.677 43.25,29.042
